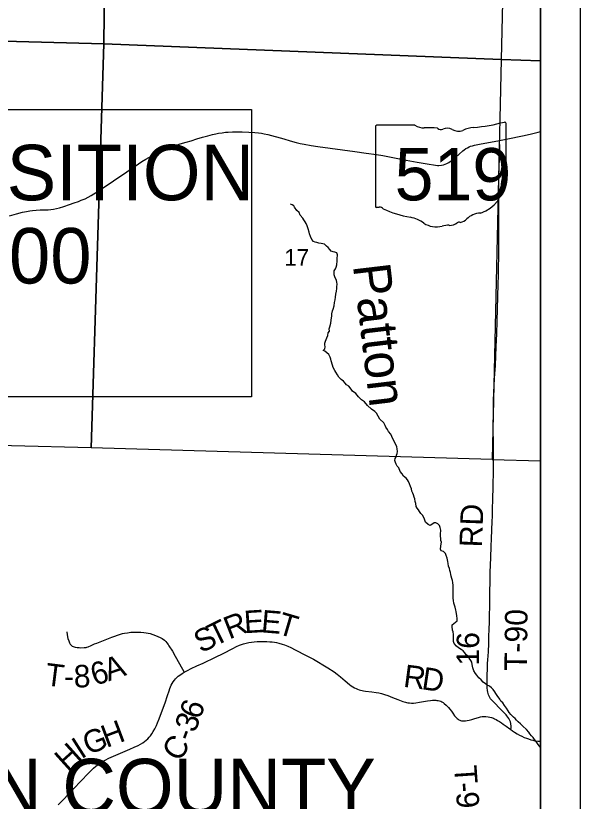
# Model space of a CAD drawing. Extents: x 0 to 34, y 0 to 22.
# Drawn here: x 8.076 to 9.5, y 16.635 to 18.617 of the extents above; entities that cross this region are included whole.
import ezdxf

# ---------------------------------------------------------------- set-up
doc = ezdxf.new("R2010")
doc.units = 0
for name, color, linetype in [('GM_X_Corporation', 7, 'Continuous'), ('GM_X_County_Road', 7, 'Continuous'), ('GM_X_County_Road_Text', 7, 'Continuous'), ('GM_X_Minor_River', 7, 'Continuous'), ('GM_X_Minor_River_Text', 7, 'Continuous'), ('GM_X_Section_Text', 7, 'Continuous'), ('GM_X_State_Location', 7, 'Continuous'), ('GM_X_State_Route', 7, 'Continuous'), ('GM_X_State_Shield', 7, 'Continuous'), ('GM_X_Township_Road', 7, 'Continuous'), ('GM_X_Township_Road_Text', 7, 'Continuous'), ('SH_Data', 7, 'Continuous'), ('SH_Text', 7, 'Continuous')]:
    doc.layers.add(name, color=color, linetype=linetype)

msp = doc.modelspace()

# ---------------------------------------------------------------- linework, layer by layer
at = {"layer": 'GM_X_Corporation'}
for points in [[(9.4, 16.4853), (9.4, 20.4), (2.6, 20.4), (2.6, 16.6918), (3.1555, 16.6686), (3.1684, 16.6682), (4.0515, 16.6368), (4.1011, 16.6362), (4.1867, 16.6352), (4.5473, 16.6256), (4.6351, 16.6229), (5.4202, 16.5982), (6.0834, 16.5816), (6.2194, 16.578), (8.0963, 16.5226), (9.09, 16.4927)], [(9.4, 16.4853), (9.4, 20.4), (6.2895, 20.4), (6.2595, 19.6124), (6.2942, 19.6131), (6.2926, 19.1539), (6.292, 18.5898), (6.2786, 18.5898), (6.2744, 18.4654), (6.2729, 18.2077), (6.2194, 16.578), (8.0963, 16.5226), (9.09, 16.4927)], [(8.2946, 19.5667), (8.3101, 19.5662), (8.2986, 18.5464), (7.291, 18.5737), (7.3046, 19.5855)], [(9.3157, 19.5601), (9.3252, 19.5587), (9.3006, 18.5069), (8.2986, 18.5464), (8.3101, 19.5662)], [(9.4, 18.5032), (9.4, 19.5563), (9.3252, 19.5587), (9.3006, 18.5069)], [(8.2986, 18.5464), (8.2669, 17.5271), (7.261, 17.5518), (7.291, 18.5737)], [(8.2986, 18.5464), (9.3006, 18.5069), (9.2775, 17.4976), (8.2669, 17.5271)], [(9.4, 17.4939), (9.4, 18.5032), (9.3006, 18.5069), (9.2775, 17.4976)]]:
    msp.add_lwpolyline(points, close=True, dxfattribs=at)
at = {"layer": 'GM_X_County_Road'}
msp.add_lwpolyline([(8.1832, 16.6253), (8.1961, 16.6386), (8.2229, 16.667), (8.2402, 16.6855), (8.2597, 16.7057), (8.2651, 16.711), (8.2723, 16.7179), (8.2779, 16.7229), (8.284, 16.7276), (8.2892, 16.7312), (8.2967, 16.7357), (8.3016, 16.7384), (8.3111, 16.743), (8.3289, 16.7513), (8.3467, 16.7589), (8.3641, 16.7665), (8.3752, 16.7713), (8.3851, 16.7758), (8.3912, 16.779), (8.3968, 16.7824), (8.4008, 16.7853), (8.4051, 16.7885), (8.4092, 16.7922), (8.4132, 16.7961), (8.4159, 16.7995), (8.4195, 16.8046), (8.4233, 16.8106), (8.427, 16.8177), (8.431, 16.8261), (8.4339, 16.8327), (8.4379, 16.8427), (8.444, 16.8586), (8.4528, 16.8827), (8.4591, 16.9014), (8.4633, 16.9136), (8.4653, 16.9191), (8.4687, 16.9273), (8.4709, 16.9318), (8.4735, 16.9362), (8.4767, 16.9406), (8.4793, 16.9437), (8.4827, 16.9473), (8.4862, 16.9503), (8.4899, 16.9531), (8.496, 16.9571), (8.5013, 16.9602), (8.5091, 16.9646), (8.5188, 16.9695), (8.5334, 16.9762), (8.5491, 16.9835), (8.5805, 16.9984), (8.5996, 17.0079), (8.6234, 17.0201), (8.6334, 17.0251), (8.6404, 17.0283), (8.6456, 17.0302), (8.6508, 17.032), (8.6574, 17.0339), (8.6641, 17.0354), (8.6707, 17.0365), (8.6774, 17.0373), (8.685, 17.0378), (8.693, 17.0379), (8.7097, 17.0377), (8.7172, 17.0373), (8.723, 17.0369), (8.7288, 17.0361), (8.7341, 17.035), (8.7401, 17.0336), (8.7479, 17.0314), (8.7542, 17.0293), (8.7628, 17.0257), (8.77, 17.0225), (8.7814, 17.017), (8.8084, 17.0029), (8.827, 16.9929), (8.8399, 16.9857), (8.8511, 16.9793), (8.8632, 16.9717), (8.879, 16.9612), (8.8872, 16.9553), (8.8952, 16.9487), (8.9072, 16.9382), (8.9181, 16.9291), (8.9224, 16.9259), (8.9267, 16.9231), (8.9306, 16.9209), (8.9345, 16.9189), (8.9385, 16.9172), (8.9423, 16.9159), (8.9458, 16.9148), (8.9496, 16.9138), (8.9536, 16.913), (8.9585, 16.9122), (8.9742, 16.9106), (8.9856, 16.9093), (8.992, 16.9083), (8.9989, 16.9066), (9.0066, 16.9042), (9.0151, 16.9012), (9.0266, 16.8968), (9.0403, 16.8911), (9.0529, 16.8863), (9.0589, 16.8844), (9.0617, 16.8838), (9.0649, 16.8832), (9.0693, 16.8827), (9.0741, 16.8825), (9.0792, 16.8826), (9.085, 16.883), (9.0946, 16.8847), (9.1046, 16.8866), (9.1144, 16.8881), (9.1222, 16.8892), (9.1273, 16.8895), (9.1321, 16.8897), (9.1356, 16.8895), (9.1386, 16.8893), (9.1413, 16.889), (9.1448, 16.8882), (9.148, 16.8872), (9.151, 16.8857), (9.1544, 16.8835), (9.1571, 16.8816), (9.1617, 16.8774), (9.1646, 16.8745), (9.1676, 16.8713), (9.1708, 16.8671), (9.1749, 16.8622), (9.1783, 16.8572), (9.1832, 16.8504), (9.187, 16.8461), (9.1894, 16.8436), (9.1917, 16.8417), (9.1939, 16.8403), (9.196, 16.8393), (9.1981, 16.8384), (9.2005, 16.8377), (9.203, 16.8373), (9.2107, 16.8374), (9.2146, 16.8381), (9.2197, 16.8393), (9.2263, 16.8411), (9.2342, 16.8435), (9.2437, 16.8462), (9.2486, 16.8475), (9.2522, 16.8482), (9.2567, 16.8485), (9.2618, 16.8482), (9.2673, 16.8477), (9.2716, 16.847), (9.2763, 16.8457), (9.2812, 16.8441), (9.2841, 16.8428), (9.2875, 16.8411), (9.2913, 16.8389), (9.2959, 16.8359), (9.301, 16.8323), (9.3059, 16.8289), (9.3128, 16.8239), (9.3224, 16.8171), (9.3248, 16.8156), (9.3291, 16.8125), (9.3342, 16.8091), (9.3412, 16.8046), (9.347, 16.8013), (9.3525, 16.7986), (9.3586, 16.7958), (9.3642, 16.7936), (9.3694, 16.7918), (9.3749, 16.79), (9.3805, 16.7886), (9.3858, 16.7875), (9.3927, 16.7865), (9.3984, 16.786), (9.4, 16.7859)], dxfattribs=at)
at = {"layer": 'GM_X_Minor_River'}
for points in [[(8.8199, 18.0599), (8.8174, 18.0666), (8.8161, 18.0715), (8.8135, 18.0797), (8.8109, 18.0871), (8.8088, 18.0927), (8.8064, 18.0975), (8.8032, 18.1023), (8.8, 18.1067), (8.794, 18.114), (8.7907, 18.1207), (8.7852, 18.1258), (8.7792, 18.1339), (8.7779, 18.138), (8.7733, 18.1401), (8.7689, 18.1418)], [(9.0381, 17.4803), (9.0357, 17.4852), (9.0344, 17.4896), (9.0323, 17.4949), (9.0329, 17.4994), (9.0354, 17.504), (9.0367, 17.5086), (9.0381, 17.5128), (9.0387, 17.5173), (9.0384, 17.5241), (9.0375, 17.5294), (9.0338, 17.5368), (9.0273, 17.5494), (9.0219, 17.5613), (9.0167, 17.5679), (9.0135, 17.5734), (9.0099, 17.5793), (9.0082, 17.5834), (9.0049, 17.5897), (8.9943, 17.5995), (8.9858, 17.6139), (8.9815, 17.6183), (8.9737, 17.6241), (8.9638, 17.6335), (8.9559, 17.643), (8.9485, 17.6477), (8.941, 17.6557), (8.9342, 17.6638), (8.9253, 17.6699), (8.9225, 17.6747), (8.9161, 17.682), (8.9103, 17.6859), (8.9067, 17.69), (8.9027, 17.6947), (8.8969, 17.6994), (8.8913, 17.7053), (8.8877, 17.7108), (8.8833, 17.7174), (8.8809, 17.7219), (8.8772, 17.7296), (8.875, 17.7356), (8.872, 17.7461), (8.8711, 17.7509), (8.8694, 17.7554), (8.8657, 17.7624), (8.8606, 17.7668), (8.8559, 17.7711), (8.8517, 17.7721), (8.8557, 17.7764), (8.8567, 17.7813), (8.8561, 17.787), (8.8556, 17.7911), (8.8573, 17.7964), (8.8608, 17.8045), (8.8632, 17.8102), (8.8645, 17.8166), (8.8673, 17.8216), (8.8671, 17.8273), (8.8685, 17.8319), (8.8712, 17.8414), (8.8717, 17.8493), (8.8735, 17.8599), (8.8737, 17.8648), (8.875, 17.8728), (8.8767, 17.877), (8.8791, 17.8853), (8.8799, 17.8937), (8.8816, 17.9001), (8.8828, 17.907), (8.8837, 17.9149), (8.8853, 17.9221), (8.8862, 17.9289), (8.8864, 17.9331), (8.8866, 17.9399), (8.886, 17.9447), (8.8851, 17.9492), (8.881, 17.9585), (8.8796, 17.9633), (8.8791, 17.9675), (8.8797, 17.9731), (8.8825, 17.9785), (8.8842, 17.9831), (8.8863, 17.9884), (8.8871, 17.999), (8.8873, 18.0035), (8.8877, 18.0137), (8.8863, 18.0189), (8.8813, 18.021), (8.8771, 18.0216), (8.8717, 18.0233), (8.8686, 18.0274), (8.8646, 18.0321), (8.8599, 18.0361), (8.8548, 18.0408), (8.8467, 18.0424), (8.8406, 18.0433), (8.836, 18.0447), (8.8314, 18.046), (8.8272, 18.0474), (8.8228, 18.0529), (8.8199, 18.0599)], [(9.2764, 16.9213), (9.2709, 16.9249), (9.2655, 16.9277), (9.2608, 16.9313), (9.2554, 16.9349), (9.2502, 16.9408), (9.2439, 16.9462), (9.2388, 16.9529), (9.2356, 16.9573), (9.2319, 16.964), (9.2294, 16.9718), (9.2272, 16.9797), (9.2262, 16.9861), (9.2241, 16.9902), (9.2197, 16.9961), (9.2169, 17.0005), (9.2122, 17.0045), (9.2086, 17.0097), (9.2047, 17.0141), (9.1996, 17.0177), (9.1926, 17.022), (9.1879, 17.0259), (9.182, 17.0325), (9.1806, 17.0378), (9.18, 17.0461), (9.18, 17.0552), (9.1794, 17.0619), (9.1777, 17.0664), (9.1766, 17.0754), (9.1768, 17.0796), (9.1853, 17.0871), (9.1894, 17.0903), (9.1899, 17.096), (9.1886, 17.1023), (9.187, 17.1132), (9.1865, 17.1174), (9.1843, 17.1245), (9.1813, 17.1346), (9.1799, 17.141), (9.1793, 17.1474), (9.1797, 17.1583), (9.1794, 17.167), (9.1795, 17.1746), (9.1793, 17.1795), (9.1783, 17.187), (9.1774, 17.1915), (9.176, 17.1971), (9.1743, 17.2024), (9.1734, 17.2069), (9.1724, 17.2117), (9.1707, 17.217), (9.1698, 17.2218), (9.1681, 17.2278), (9.1671, 17.2346), (9.1661, 17.2398), (9.1647, 17.2481), (9.1621, 17.2548), (9.1605, 17.2597), (9.1549, 17.2651), (9.1488, 17.2668), (9.1479, 17.2709), (9.1484, 17.2785), (9.1493, 17.2842), (9.1499, 17.2887), (9.1482, 17.2932), (9.1477, 17.3087), (9.1481, 17.3185), (9.1467, 17.3256), (9.1446, 17.3305), (9.1406, 17.3352), (9.136, 17.3377), (9.1314, 17.3376), (9.1259, 17.3332), (9.1218, 17.3304), (9.1164, 17.3333), (9.1097, 17.3391), (9.1068, 17.3465), (9.103, 17.3558), (9.0983, 17.3609), (9.0947, 17.3657), (9.0919, 17.3701), (9.0883, 17.3745), (9.0862, 17.379), (9.0852, 17.3865), (9.0835, 17.3914), (9.0825, 17.3978), (9.0808, 17.4022), (9.0795, 17.4082), (9.0774, 17.4123), (9.0754, 17.4175), (9.074, 17.4231), (9.0715, 17.4294), (9.0694, 17.4362), (9.0669, 17.4417), (9.0641, 17.4462), (9.0609, 17.4502), (9.0546, 17.4556), (9.0506, 17.4612), (9.0458, 17.4674), (9.0421, 17.4763), (9.0381, 17.4803)], [(9.4, 16.7683), (9.3996, 16.769), (9.3975, 16.7735), (9.3939, 16.7779), (9.3891, 16.7853), (9.3847, 16.7908), (9.3808, 16.7952), (9.3772, 16.7996), (9.3732, 16.8048), (9.37, 16.8088), (9.3641, 16.8158), (9.3555, 16.8238), (9.3495, 16.8297), (9.3437, 16.8348), (9.3393, 16.8391), (9.3354, 16.8432), (9.3318, 16.8472), (9.3251, 16.8538), (9.3208, 16.8589), (9.318, 16.863), (9.3139, 16.8693), (9.3091, 16.8763), (9.3051, 16.883), (9.3, 16.8873), (9.2968, 16.8921), (9.2907, 16.9017), (9.2871, 16.9069), (9.2843, 16.911), (9.2803, 16.9165), (9.2764, 16.9213)]]:
    msp.add_lwpolyline(points, dxfattribs=at)
at = {"layer": 'GM_X_State_Route'}
msp.add_lwpolyline([(8.0609, 18.1122), (8.0786, 18.1174), (8.0931, 18.1212), (8.0988, 18.1225), (8.1038, 18.1236), (8.1121, 18.1249), (8.1189, 18.1257), (8.1277, 18.1266), (8.138, 18.1271), (8.1521, 18.1274), (8.1582, 18.1278), (8.1648, 18.1285), (8.1718, 18.1294), (8.1788, 18.1306), (8.1867, 18.1324), (8.1979, 18.1358), (8.2122, 18.1407), (8.2239, 18.145), (8.2346, 18.1489), (8.2414, 18.1515), (8.251, 18.1555), (8.2588, 18.1592), (8.2669, 18.1637), (8.2731, 18.1675), (8.2816, 18.173), (8.3226, 18.2003), (8.3569, 18.2234), (8.3776, 18.2376), (8.3947, 18.2491), (8.4041, 18.2551), (8.4121, 18.2596), (8.422, 18.2646), (8.4451, 18.2761), (8.4537, 18.2803), (8.4628, 18.2841), (8.4716, 18.2875), (8.4819, 18.2909), (8.4914, 18.294), (8.5062, 18.2984), (8.5186, 18.3018), (8.5329, 18.3064), (8.5477, 18.3108), (8.5605, 18.3141), (8.5727, 18.3173), (8.5807, 18.3192), (8.5879, 18.3206), (8.597, 18.322), (8.6056, 18.3232), (8.6124, 18.3237), (8.6232, 18.3241), (8.6333, 18.3244), (8.6476, 18.3241), (8.664, 18.3233), (8.6793, 18.3223), (8.6883, 18.3216), (8.6962, 18.3206), (8.703, 18.3196), (8.7124, 18.3177), (8.7217, 18.3155), (8.7307, 18.313), (8.7462, 18.3081), (8.774, 18.2996), (8.7837, 18.2971), (8.7938, 18.2948), (8.804, 18.2929), (8.8211, 18.29), (8.8384, 18.2876), (8.9316, 18.2751), (8.9601, 18.2709), (8.9862, 18.2671), (9.0018, 18.2643), (9.0612, 18.2529), (9.0884, 18.2481), (9.114, 18.2435), (9.1351, 18.2402), (9.1397, 18.2397), (9.1435, 18.2396), (9.15, 18.2401), (9.1548, 18.2412), (9.1596, 18.2426), (9.1638, 18.2443), (9.1686, 18.2468), (9.1723, 18.2491), (9.1759, 18.2516), (9.1807, 18.2555), (9.185, 18.2595), (9.2035, 18.2762), (9.207, 18.2789), (9.2117, 18.2822), (9.2155, 18.2844), (9.2196, 18.2863), (9.2234, 18.2878), (9.2282, 18.2894), (9.2335, 18.2909), (9.2415, 18.2927), (9.2498, 18.2942), (9.292, 18.3018), (9.2965, 18.3026), (9.3169, 18.3066), (9.3546, 18.3146), (9.3736, 18.3186), (9.3941, 18.3233), (9.4, 18.325)], dxfattribs=at)
at = {"layer": 'GM_X_State_Shield'}
for p, q in [((9.3128, 18.2411), (9.3128, 18.3458)), ((8.9832, 18.3374), (8.9832, 18.1373)), ((9.083, 18.3408), (8.9865, 18.3408)), ((9.3128, 18.2411), (9.3128, 18.2411))]:
    msp.add_line(p, q, dxfattribs=at)
for centre, major_axis, start_param, end_param in [((9.1954, 18.6137), (0.3495, 0), 4.814394, 5.042369), ((9.3092, 18.3462), (0.00367, 0), 6.141152, 7.989035), ((8.987, 18.3378), (0.00382, 0), 1.712693, 3.28349), ((9.106, 18.3641), (0.037, 0), 4.042523, 4.731795), ((9.1183, 18.2285), (0.133, 0), 1.404758, 1.657858), ((9.1485, 18.3388), (0.0107, 0), 3.836095, 5.185415), ((9.1641, 18.3157), (0.0222, 0), 0.950623, 2.079405), ((9.1928, 18.3474), (0.0267, 0), 4.081561, 5.145723), ((9.24, 18.2797), (0.0703, 0), 1.699011, 2.107814), ((9.312, 18.2334), (0.00568, 0), 1.883978, 3.671073), ((9.2759, 18.2202), (0.0341, 0), 5.934695, 6.695948), ((9.3089, 18.2407), (0.00393, 0), 5.05454, 6.418171), ((9.326, 18.1973), (0.0248, 0), 2.387724, 3.262537), ((9.215, 18.184), (0.0874, 0), 5.101752, 6.440018), ((8.9871, 18.1368), (0.00385, 0), 3.00124, 4.508301), ((8.9876, 18.1573), (0.0294, 0), 4.665946, 4.897461), ((8.9937, 18.1257), (0.0106, 0), 0.519207, 1.627899), ((9.1275, 18.3055), (0.2524, 0), 4.195997, 4.488961), ((9.0522, 18.0474), (0.079, 0), 0.823519, 1.323587), ((9.1912, 18.1179), (0.0282, 0), 4.937069, 5.64225), ((9.2519, 18.0811), (0.0479, 0), 1.647645, 2.488434), ((9.1376, 18.1247), (0.0501, 0), 4.026481, 4.996735), ((9.1666, 18.0555), (0.0412, 0), 1.495662, 1.94098), ((9.1703, 18.1097), (0.0267, 0), 4.691044, 5.507374), ((9.1944, 18.0904), (0.00752, 0), 1.147584, 2.315152)]:
    msp.add_ellipse(centre, major_axis=major_axis, ratio=0.8, start_param=start_param, end_param=end_param, dxfattribs=at)
at = {"layer": 'GM_X_Township_Road'}
for points in [[(9.288, 17.7827), (9.2892, 17.8147), (9.2901, 17.8463), (9.2928, 17.9397), (9.2934, 17.9615), (9.2947, 18.0288), (9.295, 18.0651), (9.2949, 18.1018), (9.2949, 18.1386), (9.2947, 18.1749), (9.2948, 18.1947), (9.2949, 18.2129), (9.2952, 18.2317), (9.2968, 18.2893), (9.2967, 18.297), (9.2965, 18.3026)], [(9.3248, 16.8156), (9.3256, 16.82), (9.3259, 16.8233), (9.3252, 16.8313), (9.3239, 16.8348), (9.322, 16.8389), (9.3195, 16.8433), (9.3175, 16.8468), (9.3152, 16.8499), (9.3127, 16.853), (9.308, 16.858), (9.2982, 16.8681), (9.2827, 16.8841), (9.2793, 16.8874), (9.2763, 16.8904), (9.274, 16.8931), (9.2719, 16.8964), (9.2702, 16.8996), (9.2685, 16.9034), (9.2673, 16.9067), (9.2665, 16.9102), (9.2658, 16.9142), (9.2653, 16.9206), (9.2652, 16.9502), (9.2657, 16.9718), (9.2664, 16.9822), (9.2672, 16.9919), (9.2682, 17.0121), (9.2691, 17.0331), (9.2696, 17.0507), (9.2701, 17.0692), (9.2708, 17.0868), (9.2715, 17.107), (9.2719, 17.124), (9.2722, 17.1413), (9.2721, 17.1666), (9.2725, 17.1858), (9.2728, 17.2011), (9.2731, 17.2118), (9.2735, 17.2316), (9.2741, 17.249), (9.2745, 17.2584), (9.2749, 17.2695), (9.2753, 17.2796), (9.2762, 17.2961), (9.2772, 17.3203), (9.2782, 17.3398), (9.2784, 17.3554), (9.2789, 17.3745), (9.2796, 17.3944), (9.2801, 17.4311), (9.2808, 17.4679), (9.2814, 17.5061), (9.2811, 17.526), (9.2808, 17.5486), (9.2806, 17.5625), (9.2807, 17.5892), (9.2808, 17.6076), (9.2813, 17.6439), (9.2819, 17.6678), (9.2826, 17.6835), (9.284, 17.7024), (9.2859, 17.7345), (9.287, 17.7577), (9.288, 17.7827)], [(8.2048, 17.0625), (8.206, 17.0545), (8.2081, 17.0456), (8.2101, 17.0392), (8.212, 17.0343), (8.214, 17.031), (8.2159, 17.0287), (8.2172, 17.0274), (8.219, 17.0262), (8.2215, 17.0251), (8.2238, 17.0245), (8.2264, 17.0239), (8.2313, 17.0231), (8.2364, 17.0225), (8.2408, 17.0223), (8.2486, 17.0224), (8.2517, 17.0225), (8.2538, 17.0228), (8.2554, 17.0232), (8.2593, 17.0246), (8.2669, 17.0281), (8.275, 17.0317), (8.2808, 17.034), (8.2931, 17.039), (8.3061, 17.0439), (8.3186, 17.0486), (8.3407, 17.0563), (8.3457, 17.0577), (8.3504, 17.0587), (8.3581, 17.0601), (8.3662, 17.0612), (8.3705, 17.0616), (8.3745, 17.0617), (8.3918, 17.0613), (8.3994, 17.0607), (8.4054, 17.06), (8.41, 17.0592), (8.4153, 17.0577), (8.422, 17.0556), (8.429, 17.0529), (8.4349, 17.0506), (8.4405, 17.0481), (8.4459, 17.0452), (8.4514, 17.0414), (8.4548, 17.0378), (8.4574, 17.0343), (8.4605, 17.0304), (8.4628, 17.0268), (8.4715, 17.0132), (8.4785, 17.0011), (8.4893, 16.9812), (8.5013, 16.9602)]]:
    msp.add_lwpolyline(points, dxfattribs=at)
at = {"layer": 'SH_Data'}
for points in [[(2.5, 20.5), (9.5, 20.5), (9.5, 13.5), (2.5, 13.5)], [(2.6, 20.4), (9.4, 20.4), (9.4, 13.6), (2.6, 13.6)]]:
    msp.add_lwpolyline(points, close=True, dxfattribs=at)
at = {"layer": 'SH_Text'}
msp.add_lwpolyline([(6.9735, 18.3806), (8.6708, 18.3806), (8.6708, 17.6557), (6.9735, 17.6557)], close=True, dxfattribs=at)

# ---------------------------------------------------------------- texts
at = {"layer": 'GM_X_County_Road_Text'}
for s, rotation, p in [('E', 3.5873, (8.6536, 17.0586)), ('E', 355.1321, (8.6938, 17.0613)), ('T', 26.2181, (8.5777, 17.0245)), ('R', 21.2075, (8.6146, 17.0427)), ('T', 343.5984, (8.7332, 17.0583)), ('S', 26.3589, (8.5434, 17.0075)), ('R', 352.5361, (9.052, 16.9238)), ('D', 351.4462, (9.098, 16.9178)), ('6', 70.4006, (8.5409, 16.8388)), ('3', 70.1946, (8.5289, 16.8057)), ('H', 20.6294, (8.3051, 16.769)), ('G', 21.1124, (8.2586, 16.751)), ('I', 32.482, (8.2416, 16.7398)), ('C', 56.5167, (8.4884, 16.7317)), ('-', 69.451, (8.5205, 16.7831)), ('H', 42.0365, (8.2064, 16.7079))]:
    msp.add_text(s, height=0.0568, rotation=rotation, dxfattribs=at).set_placement(p)
at = {"layer": 'GM_X_Minor_River_Text'}
msp.add_text('Patton', height=0.09397, rotation=276.791, dxfattribs=at).set_placement((8.9265, 17.9875))
at = {"layer": 'GM_X_Section_Text'}
msp.add_text('17', height=0.04186, rotation=0, dxfattribs=at).set_placement((8.7537, 17.9864))
at = {"layer": 'GM_X_State_Location'}
for s in ['s', 'r']:
    msp.add_text(s, height=0.000189, dxfattribs=at).set_placement((9.1443, 18.224))
msp.add_text('519', height=0.000189, rotation=0, dxfattribs=at).set_placement((9.0775, 18.2102))
at = {"layer": 'GM_X_State_Shield'}
msp.add_text('519', height=0.13184, dxfattribs=at).set_placement((9.0317, 18.1514))
at = {"layer": 'GM_X_Township_Road_Text'}
for s, height, rotation, p in [('RD', 0.05682, 88.0242, (9.252, 17.2749)), ('T-90', 0.05682, 89.3094, (9.3653, 16.9633)), ('16', 0.05682, 89.3101, (9.2444, 16.9769)), ('A', 0.0568, 19.1773, (8.3103, 16.9369)), ('T', 0.0568, 352.833, (8.1484, 16.9277)), ('8', 0.0568, 1.5726, (8.2233, 16.9216)), ('6', 0.0568, 18.1088, (8.2759, 16.9256)), ('-', 0.0568, 359.2933, (8.1975, 16.9219)), ('T', 0.0568, 273.9287, (9.1816, 16.7232)), ('-', 0.0568, 274.1056, (9.1845, 16.6806)), ('9', 0.0568, 274.9285, (9.1863, 16.6565))]:
    msp.add_text(s, height=height, rotation=rotation, dxfattribs=at).set_placement(p)
at = {"layer": 'SH_Text'}
for s, p in [('END ACQUISITION', (7.0133, 18.1516)), ('STA. 14+60.00', (7.0133, 17.9416)), ('HARRISON COUNTY', (7.1536, 16.6018))]:
    msp.add_text(s, height=0.14, dxfattribs=at).set_placement(p)

doc.saveas('drawing.dxf')
